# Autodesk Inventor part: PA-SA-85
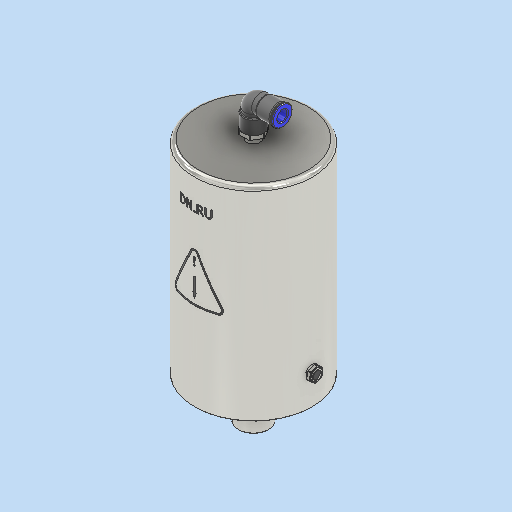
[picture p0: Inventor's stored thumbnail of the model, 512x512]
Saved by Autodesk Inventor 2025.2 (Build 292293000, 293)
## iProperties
Created: 2024-12
Part Number: PA-SA-85
Material: Типовые
Document SubType Name: Modeling
Designer: DN.RU
Density: 3.64653 g/cm^3
Appearance: По умолчанию
Description: D290-00341
Mass: 3090 g
Surface Area: 625.481 cm^2
Volume: 847.38 cm^3
Sending System: Autodesk Inventor 2025
Preprocessor: ST-DEVELOPER v20
Title: Пневмопривод с возвратными пружинами DN.ru
Author: DN.RU
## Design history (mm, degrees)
feature "Твердое тело1"
sketch "Эскиз1"
  geometry: C1 r 7 at (0, -3.994) reference; 1 further point
extrude "Выдавливание1" join sketch "Эскиз1" distance "d0" = 10; taper "d1" = 0 deg
node "Непосредственное редактирование1"
sketch "Эскиз2"
  geometry: L1 (-5.657, 0)-(0, 5.657); L2 (0, 5.657)-(5.657, 0); L3 (5.657, 0)-(0, -5.657); L4 (0, -5.657)-(-5.657, 0); L5 (-5.657, 0)-(5.657, 0); L6 (0, 5.657)-(0, -5.657); L7 (-5.657, 0)-(2.343, 0); C1 r 8.5 at (0, 0); 1 further point
  constraints: 14 end point, 2 midpoint, 2 parallel, 1 centre point, 1 coincident, 1 equal length, 1 horizontal, 1 perpendicular
  dimensions: "d5" = 8 distance of L1.start L1.end; "d6" = 45 deg angle of L7 L1; "d7" = 8 distance of L1.end L2.end; "d8" = 17 diameter of C1
extrude "Выдавливание2" join sketch "Эскиз2" distance "d9" = 16; taper "d10" = 0 deg
sketch "Эскиз3"
  geometry: C1 r 42.5 at (0, 0) reference; 1 further point
extrude "Выдавливание3" join sketch "Эскиз3" stored distance "d11" = 10; taper "d12" = 0 deg
node "Непосредственное редактирование2"
sketch "Эскиз4"
  geometry: C1 r 42.5 at (9.705, -41.274) reference; 1 further point
extrude "Выдавливание4" join sketch "Эскиз4" distance "d16" = 10; taper "d17" = 0 deg
sketch "Эскиз5"
  geometry: C1 r 11 at (0, 0) reference; C2 r 13 at (0, 0); 1 further point
  constraints: 1 centre point
  dimensions: "d19" = 2 radial gap between concentric circles of C1 C2
extrude "Выдавливание5" join sketch "Эскиз5" distance "d20" = 20; taper "d21" = 0 deg
chamfer "Фаска1" distance "d22" = 2; stored, may be unused: second distance "d23" = 2, angle "d24" = 45 deg
fillet "Сопряжение1" dims "d25" = 3
node "РабПлоскость1"
sketch "Эскиз6"
  geometry: L1 (-12.672, 51.233)-(-0.411, 51.233); L2 (-0.411, 51.233)-(-0.411, 48.121); L3 (-0.411, 48.121)-(-12.672, 48.121); L4 (-12.672, 48.121)-(-12.672, 51.233); L5 (1.758, 19.98)-(16.115, -9.265); L6 (14.319, -12.146)-(-15.009, -12.146); L7 (-16.789, -9.234)-(-1.818, 20.01); L8 (17.012, -8.824)-(2.656, 20.421); L9 (-2.708, 20.466)-(-17.68, -8.779); L10 (-15.009, -13.146)-(14.319, -13.146); L11 (-1.47, 17.4)-(1.268, 17.4); L12 (1.268, 17.4)-(1.268, 11.4); L13 (1.268, 11.4)-(-1.47, 11.4); L14 (-1.47, 11.4)-(-1.47, 17.4); L15 (-0.5, -5)-(-0.5, 5); L16 (-0.5, 5)-(0.5, 5); L17 (0.5, 5)-(0.5, -5); L18 (0.5, -5)-(-0.5, -5); L19 (-0.5, -5)-(0.5, 5); L20 (-0.5, 5)-(0.5, -5); L21 (0, -5)-(0, -8.824); L22 (0, -8.824)-(1.293, -4.923); L23 (1.293, -4.923)-(-1.269, -4.923); L24 (-1.269, -4.923)-(0, -8.824); A1 r 2 centre (-15.009, -10.146) between (-16.789, -9.234) and (-15.009, -12.146); A2 r 2 centre (-0.037, 19.099) between (1.758, 19.98) and (-1.818, 20.01); A3 r 2 centre (14.319, -10.146) between (14.319, -12.146) and (16.115, -9.265); A4 r 3 centre (-0.037, 19.099) between (2.656, 20.421) and (-2.708, 20.466); A5 r 3 centre (-15.009, -10.146) between (-17.68, -8.779) and (-15.009, -13.146); A6 r 3 centre (14.319, -10.146) between (14.319, -13.146) and (17.012, -8.824); 2 further points
  constraints: 32 end point, 12 point on circle, 6 centre point, 6 tangent, 3 midpoint, 2 equal radius, 2 parallel, 2 perpendicular, 2 vertical, 1 coincident, 1 horizontal, 9 other
  dimensions: "d27" = 2 radius of A1 (derived); "d28" = 1 distance between parallel lines of L5 L8; "d29" = 10 distance of L15.start L15.end; "d30" = 1 distance of L15.end L16.end
feature "Рельеф1" sketch "Эскиз6" dims "d31" = 0.1, "d32" = 0
node "Непосредственное редактирование3"
node "Твердое тело2"
feature "Размер1" dims "d2" = -5
feature "Размер2" dims "d3" = 2
feature "Размер3" dims "d4" = -2
feature "Перенос1" dims "d15" = 4.3
feature "Размер4" dims "d18" = 15
feature "Перенос2" dims "d47" = 7
other parameters: "d13" = 0, "d14" = 0, "d45" = 0, "d46" = 0
